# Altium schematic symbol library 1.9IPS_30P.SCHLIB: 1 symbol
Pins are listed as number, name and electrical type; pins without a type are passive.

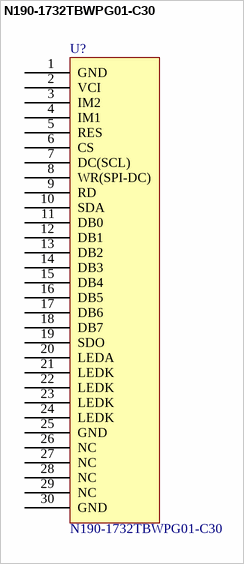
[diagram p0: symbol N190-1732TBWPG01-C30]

## N190-1732TBWPG01-C30
designator U?
1.9TFT IPS
footprint 1.9_30P_FPC_0.5mm
pins: 1 GND, 2 VCI, 3 IM2, 4 IM1, 5 RES, 6 CS, 7 DC(SCL), 8 WR(SPI-DC), 9 RD, 10 SDA, 11 DB0, 12 DB1, 13 DB2, 14 DB3, 15 DB4, 16 DB5, 17 DB6, 18 DB7, 19 SDO, 20 LEDA, 21 LEDK, 22 LEDK, 23 LEDK, 24 LEDK, 25 GND, 26 NC, 27 NC, 28 NC, 29 NC, 30 GND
